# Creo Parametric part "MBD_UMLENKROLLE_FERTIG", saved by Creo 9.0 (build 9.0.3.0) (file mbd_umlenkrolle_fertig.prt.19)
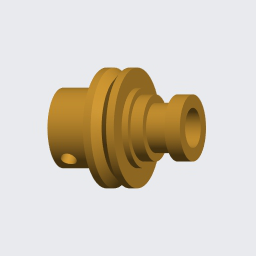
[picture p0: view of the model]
Materials in the file: STAHL

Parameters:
  WERKSTOFF = "Stahl"
  ERSTELLER = "ARINDA"
  BENENNUNG = "Umlenkrolle"
  TEILETYP = "K"
  PTC_MASTER_MATERIAL = "STAHL"
  SCHRAUBEN_GROESSE = "M3x.5"
  METRISCH = "JA"

Other parameters: MASSE, STEIGUNG, BOHR_DURCHM, GEWINDEDURCHMESSER, GEWINDEGÄNGE_PRO_INCH, GEWINDETIEFE, GEWINDELÄNGE

Created from: MBD_UMLENKROLLE.PRT

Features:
  1. coordinate system
  2. datum plane "RECHTS_Y-Z"
  3. datum plane "OBEN_X-Z"
  4. datum plane "VORNE_X-Y"
  5. datum axis
  6. datum axis
  7. datum axis
  8. datum point "PNT0"
  9. protrusion
  10. hole
  11. protrusion
  12. datum plane "DTM1", "SEC_B"
  13. annotation "Anmerkung 1"
  14. annotation "Anmerkung 2"
  15. annotation "Anmerkung 3"
  16. annotation "Anmerkung 4"

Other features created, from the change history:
  planar section "XSEC0001"

Other named items: LOGO, A_X, A_Y, A_Z, CS0, DRV_DIM_D1, DRV_DIM_D2, DRV_DIM_D5, DRV_DIM_D6, DRV_DIM_D7, DRV_DIM_D8, DRV_DIM_D9, DRV_DIM_D10, DRV_DIM_D11, DRV_DIM_D31, DRV_DIM_D32, DRV_DIM_D33, DRV_DIM_D34, DRV_DIM_D35, D35, D34, D33, D32, D31, D11, D10, D9, D8, D7, D6, D5, D2, D1, DRV_DIM_D26, D26, DRV_DIM_D25, D25, DATUM_TAG_A, GP0, DRF1, BASELINE0, BASELINE1, OAD45, OAD46, OAD47, OAD48, OAD49, OAD50, OAD51, OAD52, AE_NOTE0, AE_NOTE1, NOTE_4, SYMBOL_0, SYMBOL_2, HINTEN, LINKS, UNTEN, ORDINATEN, ANNOT_LAYER_STATE0001, ANNOT_LAYER_STATE0002, ANNOT_LAYER_STATE0003, ANNOT_LAYER_STATE0004

Layers: 01_ACHSEN, 01_ACHSEN_STD, 01_EBENEN, 01_EBENEN_STD, 01_KOORDSYS_STD, 01_PUNKTE_STD, BOHRUNGSNOTIZ, GEWINDE, SAMMELFLÄCHEN, VOLUMENGEOMETRIE

Notes: M3x.5 | GEWINDEBOHREN | 4.000 |  BOHREN (  | 2.500 | DURCH |   -(  |  ) BOHRUNG |  f| 0.01 | A | Gesamtlänge:  | Maximaler Durchmesser: | Ersteller :  | ARINDA | Benennung :  | Umlenkrolle | Maximale Länge :  | Maximaler Durchmesser :  |  n 18 | Material :  | Stahl | Masse :  | 15.650 | Flächen Poliert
